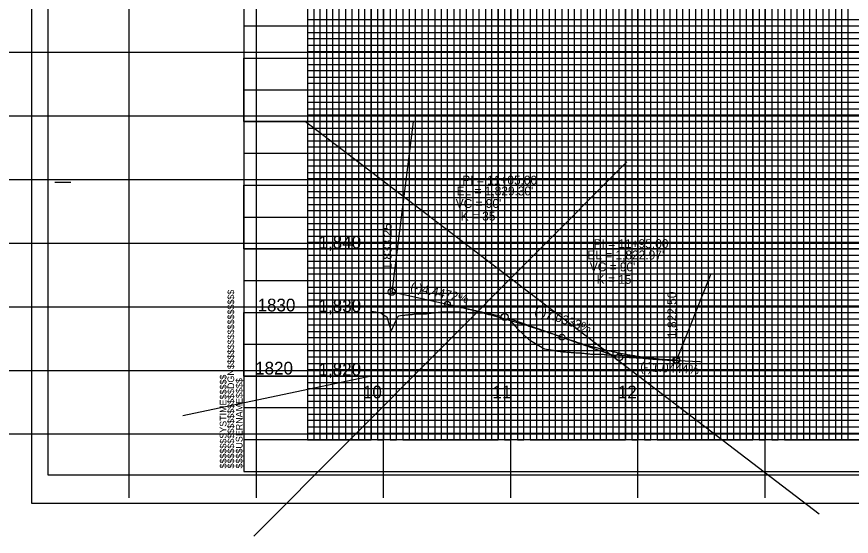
# Model space of a CAD drawing. Extents: x 553912 to 567693, y 512355 to 537539.
# Drawn here: x 559761 to 560417, y 521024 to 521433 of the extents above; entities that cross this region are included whole.
import ezdxf

# ---------------------------------------------------------------- set-up
doc = ezdxf.new("R2010")
doc.units = 0
for name, color, linetype in [('Default', 7, 'Continuous'), ('Exist Vertical Profile Ground Line', 7, 'Continuous'), ('Exist Vertical Profile Horizontal Axis Label Major', 7, 'Continuous'), ('Exist Vertical Profile Vertical Axis Label', 7, 'Continuous'), ('Old_Level_42', 7, 'Continuous'), ('Old_Level_51', 7, 'Continuous'), ('Old_Level_53', 7, 'Continuous'), ('Old_Level_54', 7, 'Continuous'), ('Prop ROW Permanent Easement CELL', 7, 'Continuous'), ('Prop Vertical Profile Curve Label', 7, 'Continuous'), ('Prop Vertical Profile Ditch Grade Right Label', 7, 'Continuous'), ('Prop Vertical Profile Grade', 7, 'Continuous'), ('Prop Vertical Profile Grade Label', 7, 'Continuous'), ('Prop VPI Label', 7, 'Continuous'), ('Sheet Profile Grid Major CELL', 7, 'Continuous'), ('Sheet Row Area Data CELL', 7, 'Continuous'), ('Sheet Summary Guardrail CELL', 7, 'Continuous')]:
    doc.layers.add(name, color=color, linetype=linetype)

msp = doc.modelspace()

# ---------------------------------------------------------------- linework, layer by layer
at = {"layer": 'Default'}
msp.add_lwpolyline([(561456.66, 522150.42), (559772.66, 522150.42), (559772.66, 521050.42), (561456.66, 521050.42)], close=True, dxfattribs=at)
at = {"layer": 'Exist Vertical Profile Ground Line'}
for points in [[(560039.66, 521201.58), (560046.99, 521200.43), (560048.85, 521198.92), (560052.01, 521197.1), (560054.97, 521187.43), (560055.59, 521186.29), (560060.34, 521196.62), (560060.68, 521197.07), (560061.38, 521197.92), (560062.81, 521198.09), (560065.6, 521198.37), (560066.23, 521198.44), (560066.85, 521198.5), (560067.48, 521198.56), (560068.1, 521198.62), (560068.73, 521198.67), (560069.36, 521198.73), (560069.98, 521198.78), (560070.61, 521198.84), (560071.24, 521198.89), (560071.86, 521198.95), (560072.49, 521199.03), (560072.81, 521199.08), (560073.11, 521199.14), (560073.74, 521199.27), (560074.37, 521199.28), (560074.99, 521199.29), (560075.62, 521199.3), (560076.24, 521199.31), (560076.87, 521199.31), (560077.5, 521199.32), (560078.12, 521199.33), (560078.75, 521199.33), (560079.38, 521199.33), (560080, 521199.32), (560080.63, 521199.32), (560081.25, 521199.32), (560081.94, 521199.31), (560082.51, 521199.34), (560083.13, 521199.38), (560083.76, 521199.59), (560084.39, 521199.68), (560085.01, 521199.76), (560085.64, 521199.83), (560086.26, 521199.91), (560086.89, 521199.98), (560087.52, 521200.06), (560088.14, 521200.13), (560088.77, 521200.2), (560089.39, 521200.27), (560090.02, 521200.34), (560090.65, 521200.4), (560091.27, 521200.46), (560091.9, 521200.53), (560092.53, 521200.59), (560093.15, 521200.65), (560093.78, 521200.7), (560094.4, 521200.76), (560095.03, 521200.81), (560095.66, 521200.86), (560096.28, 521200.91), (560096.91, 521200.96), (560097.82, 521201.03), (560098.16, 521201.03), (560098.79, 521201.02), (560099.41, 521201.01), (560100.04, 521201.01), (560100.67, 521201), (560101.29, 521200.99), (560101.92, 521200.99), (560102.24, 521200.98), (560102.54, 521200.98), (560103.17, 521200.98), (560103.8, 521200.97), (560104.42, 521200.97), (560105.05, 521200.96), (560105.68, 521200.96), (560106.3, 521200.95), (560106.93, 521200.95), (560107.55, 521200.94), (560108.18, 521200.93), (560108.81, 521200.89), (560109.43, 521200.84), (560110.06, 521200.8), (560110.68, 521200.75), (560111.31, 521200.7), (560111.94, 521200.65), (560112.56, 521200.6), (560113.19, 521200.55), (560113.82, 521200.49), (560114.44, 521200.43), (560115.07, 521200.38), (560115.84, 521200.3), (560116.32, 521200.28), (560116.95, 521200.25), (560117.57, 521200.22), (560120.57, 521200.06), (560128.05, 521200.17), (560132.8, 521198.9), (560136.5, 521197.84), (560141.43, 521196.57)], [(560141.43, 521196.57), (560148.61, 521194.5), (560149.16, 521194.01), (560149.53, 521193.59), (560154.8, 521187.58), (560163.47, 521179.49), (560164.96, 521178.44), (560175.41, 521172.24), (560176.05, 521171.86), (560179.12, 521171.33), (560180.01, 521171.17), (560180.9, 521171.02), (560181.8, 521170.87), (560182.69, 521170.71), (560183.58, 521170.56), (560184.48, 521170.41), (560185.37, 521170.26), (560186.26, 521170.11), (560187.16, 521169.97), (560188.19, 521169.79), (560188.94, 521169.73), (560189.84, 521169.65), (560190.73, 521169.58), (560191.63, 521169.5), (560192.52, 521169.42), (560193.41, 521169.35), (560194.31, 521169.28), (560195.2, 521169.21), (560196.09, 521169.14), (560196.99, 521169.07), (560197.88, 521169), (560198.77, 521168.93), (560199.67, 521168.87), (560200.56, 521168.81), (560201.45, 521168.76), (560202.35, 521168.7), (560203.24, 521168.64), (560204.13, 521168.59), (560205.03, 521168.54), (560205.92, 521168.48), (560206.81, 521168.38), (560207.71, 521168.28), (560208.6, 521168.18), (560209.5, 521168.08), (560210.39, 521167.99), (560211.28, 521167.89), (560212.18, 521167.79), (560213.07, 521167.72), (560213.96, 521167.71), (560214.86, 521167.71), (560215.75, 521167.7), (560216.64, 521167.69), (560217.54, 521167.69), (560218.43, 521167.68), (560219.32, 521167.67), (560220.22, 521167.67), (560221.26, 521167.67), (560222, 521167.58), (560222.9, 521167.48), (560223.79, 521167.38), (560224.69, 521167.27), (560225.84, 521167.14), (560234.67, 521166.82), (560239.73, 521166.52), (560252.02, 521164.76), (560255.26, 521164.29), (560257.81, 521163.97), (560264.18, 521163.58), (560272.78, 521163.05), (560280.74, 521162.75), (560298.08, 521161.98), (560298.71, 521161.98)]]:
    msp.add_lwpolyline(points, dxfattribs=at)
at = {"layer": 'Old_Level_42'}
for p, q in [((559989.66, 522125.42), (559989.66, 521100.42)), ((560039.66, 522125.42), (560039.66, 521100.42)), ((560089.66, 522125.42), (560089.66, 521100.42)), ((560139.66, 522125.42), (560139.66, 521100.42)), ((560189.66, 522125.42), (560189.66, 521100.42)), ((560239.66, 522125.42), (560239.66, 521100.42)), ((560289.66, 522125.42), (560289.66, 521100.42)), ((560339.66, 522125.42), (560339.66, 521100.42)), ((560389.66, 522125.42), (560389.66, 521100.42)), ((559939.66, 521400.42), (561439.66, 521400.42)), ((559939.66, 521350.42), (561439.66, 521350.42)), ((559939.66, 521300.42), (561439.66, 521300.42)), ((559939.66, 521250.42), (561439.66, 521250.42)), ((559939.66, 521200.42), (561439.66, 521200.42)), ((559939.66, 521150.42), (561439.66, 521150.42))]:
    msp.add_line(p, q, dxfattribs=at)
at = {"layer": 'Old_Level_51'}
msp.add_lwpolyline([(561452.16, 522127.97), (559785.66, 522127.97), (559785.66, 521072.87), (561452.16, 521072.87)], close=True, dxfattribs=at)
at = {"layer": 'Old_Level_53'}
for p, q in [((559791.16, 521302.92), (559803.66, 521302.92)), ((561439.66, 521100.42), (559939.66, 521100.42)), ((559939.66, 521075.42), (559939.66, 521075.42)), ((559939.66, 521075.42), (559939.66, 521075.42)), ((559939.66, 521075.42), (559939.66, 521075.42)), ((559939.66, 521075.42), (559939.66, 521075.42)), ((559939.66, 521075.42), (559939.66, 521075.42)), ((559939.66, 521075.42), (559939.66, 521075.42))]:
    msp.add_line(p, q, dxfattribs=at)
msp.add_lwpolyline([(561439.66, 522125.42), (559939.66, 522125.42), (559939.66, 521075.42), (561439.66, 521075.42)], close=True, dxfattribs=at)
msp.add_lwpolyline([(559977.16, 521075.42), (559977.16, 521075.42)], dxfattribs=at)
at = {"layer": 'Old_Level_54'}
for points in [[(559989.66, 522125.42), (559989.66, 521100.42), (560039.66, 521100.42), (560039.66, 522125.42)], [(560089.66, 522125.42), (560089.66, 521100.42), (560139.66, 521100.42), (560139.66, 522125.42)], [(560189.66, 522125.42), (560189.66, 521100.42), (560239.66, 521100.42), (560239.66, 522125.42)], [(560289.66, 522125.42), (560289.66, 521100.42), (560339.66, 521100.42), (560339.66, 522125.42)], [(560389.66, 522125.42), (560389.66, 521100.42), (560439.66, 521100.42), (560439.66, 522125.42)], [(561439.66, 521350.42), (559939.66, 521350.42), (559939.66, 521400.42), (561439.66, 521400.42)], [(561439.66, 521250.42), (559939.66, 521250.42), (559939.66, 521300.42), (561439.66, 521300.42)], [(561439.66, 521150.42), (559939.66, 521150.42), (559939.66, 521200.42), (561439.66, 521200.42)]]:
    msp.add_lwpolyline(points, dxfattribs=at)
at = {"layer": 'Prop ROW Permanent Easement CELL'}
for points in [[(560014.66, 521100.42), (560014.66, 522125.42)], [(560064.66, 522125.42), (560064.66, 521100.42), (560114.66, 521100.42), (560114.66, 522125.42)], [(560164.66, 522125.42), (560164.66, 521100.42), (560214.66, 521100.42), (560214.66, 522125.42)], [(560264.66, 522125.42), (560264.66, 521100.42), (560314.66, 521100.42), (560314.66, 522125.42)], [(560364.66, 522125.42), (560364.66, 521100.42), (560414.66, 521100.42), (560414.66, 522125.42)], [(561439.66, 521425.42), (559939.66, 521425.42), (559939.66, 521375.42), (561439.66, 521375.42)], [(561439.66, 521325.42), (559939.66, 521325.42), (559939.66, 521275.42), (561439.66, 521275.42)], [(561439.66, 521225.42), (559939.66, 521225.42), (559939.66, 521175.42), (561439.66, 521175.42)], [(561439.66, 521125.42), (559939.66, 521125.42)]]:
    msp.add_lwpolyline(points, dxfattribs=at)
at = {"layer": 'Prop Vertical Profile Curve Label'}
for centre in [(560099.66, 521206.93), (560189.66, 521181.1), (560189.66, 521181.1), (560279.66, 521162.92)]:
    msp.add_circle(centre, 2.25, dxfattribs=at)
at = {"layer": 'Prop Vertical Profile Ditch Grade Right Label'}
msp.add_line((560039.66, 521150.42), (559891.72, 521119.2), dxfattribs=at)
at = {"layer": 'Prop Vertical Profile Grade'}
msp.add_line((560055.84, 521216.67), (560099.66, 521206.93), dxfattribs=at)
for points in [[(560099.66, 521206.93), (560101.46, 521206.53), (560103.26, 521206.12), (560105.06, 521205.71), (560106.86, 521205.29), (560108.66, 521204.87), (560110.46, 521204.44), (560112.26, 521204.01), (560114.06, 521203.58), (560115.86, 521203.14), (560117.66, 521202.69), (560119.46, 521202.24), (560121.26, 521201.79), (560123.06, 521201.33), (560124.86, 521200.87), (560126.66, 521200.4), (560128.46, 521199.93), (560130.26, 521199.45), (560132.06, 521198.97), (560133.86, 521198.48), (560135.66, 521197.99), (560137.46, 521197.5), (560139.26, 521197), (560141.06, 521196.49), (560142.86, 521195.98), (560144.66, 521195.47), (560146.46, 521194.95), (560148.26, 521194.43), (560150.06, 521193.9), (560151.86, 521193.36), (560153.66, 521192.83), (560155.46, 521192.28), (560157.26, 521191.74), (560159.06, 521191.19), (560160.86, 521190.63), (560162.66, 521190.07), (560164.46, 521189.5), (560166.26, 521188.93), (560168.06, 521188.36), (560169.86, 521187.78), (560171.66, 521187.2), (560173.46, 521186.61), (560175.26, 521186.01), (560177.06, 521185.42), (560178.86, 521184.81), (560180.66, 521184.2), (560182.46, 521183.59), (560184.26, 521182.98), (560186.06, 521182.35), (560187.86, 521181.73), (560189.66, 521181.1)], [(560189.66, 521181.1), (560191.46, 521180.47), (560193.26, 521179.85), (560195.06, 521179.25), (560196.86, 521178.65), (560198.66, 521178.07), (560200.46, 521177.49), (560202.26, 521176.93), (560204.06, 521176.38), (560205.86, 521175.84), (560207.66, 521175.31), (560209.46, 521174.79), (560211.26, 521174.28), (560213.06, 521173.78), (560214.86, 521173.29), (560216.66, 521172.82), (560218.46, 521172.35), (560220.26, 521171.89), (560222.06, 521171.45), (560223.86, 521171.02), (560225.66, 521170.59), (560227.46, 521170.18), (560229.26, 521169.78), (560231.06, 521169.39), (560232.86, 521169.01), (560234.66, 521168.64), (560236.46, 521168.28), (560238.26, 521167.94), (560240.06, 521167.6), (560241.86, 521167.27), (560243.66, 521166.96), (560245.46, 521166.65), (560247.26, 521166.36), (560249.06, 521166.08), (560250.86, 521165.81), (560252.66, 521165.55), (560254.46, 521165.3), (560256.26, 521165.06), (560258.06, 521164.83), (560259.86, 521164.61), (560261.66, 521164.4), (560263.46, 521164.21), (560265.26, 521164.02), (560267.06, 521163.85), (560268.86, 521163.68), (560270.66, 521163.53), (560272.46, 521163.39), (560274.26, 521163.25), (560276.06, 521163.13), (560277.86, 521163.02), (560279.66, 521162.92)]]:
    msp.add_spline(points, degree=3, dxfattribs=at)
at = {"layer": 'Prop VPI Label'}
for p, q in [((559988.16, 521350.45), (560392, 521042.13)), ((560072.78, 521350.26), (560055.84, 521216.67)), ((560186.69, 521350.26), (560072.78, 521350.26)), ((559947.48, 521024.5), (560240.64, 521318.9)), ((560306.6, 521230.7), (560279.66, 521162.92)), ((560306.6, 521230.7), (560413.01, 521230.46)), ((560099.66, 521206.93), (560141.98, 521197.52)), ((560189.66, 521181.1), (560147.25, 521196.01)), ((560189.66, 521181.1), (560232.07, 521166.19)), ((560279.66, 521162.92), (560237.41, 521165.13))]:
    msp.add_line(p, q, dxfattribs=at)
for centre in [(560055.84, 521216.67), (560144.66, 521196.92), (560234.66, 521165.27), (560279.66, 521162.92)]:
    msp.add_circle(centre, 2.75, dxfattribs=at)
at = {"layer": 'Sheet Profile Grid Major CELL'}
for p, q in [((559849.45, 521054.67), (559849.45, 522254.67)), ((559949.45, 521054.67), (559949.45, 522254.67)), ((560049.45, 521054.67), (560049.45, 522254.67)), ((560149.45, 521054.67), (560149.45, 522254.67)), ((560249.45, 521054.67), (560249.45, 522254.67)), ((560349.45, 521054.67), (560349.45, 522254.67)), ((563849.45, 521404.67), (557249.45, 521404.67)), ((563849.45, 521354.67), (557249.45, 521354.67)), ((563849.45, 521304.67), (557249.45, 521304.67)), ((563849.45, 521254.67), (557249.45, 521254.67)), ((563849.45, 521204.67), (557249.45, 521204.67)), ((563849.45, 521154.67), (557249.45, 521154.67)), ((563849.45, 521104.67), (557249.45, 521104.67))]:
    msp.add_line(p, q, dxfattribs=at)
at = {"layer": 'Sheet Row Area Data CELL'}
for p, q in [((559772.66, 522150.42), (559772.66, 521050.42)), ((559772.66, 521050.42), (561456.66, 521050.42))]:
    msp.add_line(p, q, dxfattribs=at)
at = {"layer": 'Sheet Summary Guardrail CELL'}
for points in [[(559994.66, 522125.42), (559994.66, 521100.42), (559999.66, 521100.42), (559999.66, 522125.42)], [(560004.66, 522125.42), (560004.66, 521100.42), (560009.66, 521100.42), (560009.66, 522125.42)], [(560019.66, 522125.42), (560019.66, 521100.42), (560024.66, 521100.42), (560024.66, 522125.42)], [(560029.66, 522125.42), (560029.66, 521100.42), (560034.66, 521100.42), (560034.66, 522125.42)], [(560044.66, 522125.42), (560044.66, 521100.42), (560049.66, 521100.42), (560049.66, 522125.42)], [(560054.66, 522125.42), (560054.66, 521100.42), (560059.66, 521100.42), (560059.66, 522125.42)], [(560069.66, 522125.42), (560069.66, 521100.42), (560074.66, 521100.42), (560074.66, 522125.42)], [(560079.66, 522125.42), (560079.66, 521100.42), (560084.66, 521100.42), (560084.66, 522125.42)], [(560094.66, 522125.42), (560094.66, 521100.42), (560099.66, 521100.42), (560099.66, 522125.42)], [(560104.66, 522125.42), (560104.66, 521100.42), (560109.66, 521100.42), (560109.66, 522125.42)], [(560119.66, 522125.42), (560119.66, 521100.42), (560124.66, 521100.42), (560124.66, 522125.42)], [(560129.66, 522125.42), (560129.66, 521100.42), (560134.66, 521100.42), (560134.66, 522125.42)], [(560144.66, 522125.42), (560144.66, 521100.42), (560149.66, 521100.42), (560149.66, 522125.42)], [(560154.66, 521100.42), (560159.66, 521100.42), (560159.66, 522125.42)], [(560154.66, 522125.42), (560154.66, 521100.42)], [(560169.66, 522125.42), (560169.66, 521100.42), (560174.66, 521100.42), (560174.66, 522125.42)], [(560179.66, 522125.42), (560179.66, 521100.42), (560184.66, 521100.42), (560184.66, 522125.42)], [(560194.66, 522125.42), (560194.66, 521100.42), (560199.66, 521100.42), (560199.66, 522125.42)], [(560204.66, 522125.42), (560204.66, 521100.42), (560209.66, 521100.42), (560209.66, 522125.42)], [(560219.66, 522125.42), (560219.66, 521100.42), (560224.66, 521100.42), (560224.66, 522125.42)], [(560229.66, 522125.42), (560229.66, 521100.42), (560234.66, 521100.42), (560234.66, 522125.42)], [(560244.66, 522125.42), (560244.66, 521100.42), (560249.66, 521100.42), (560249.66, 522125.42)], [(560254.66, 522125.42), (560254.66, 521100.42), (560259.66, 521100.42), (560259.66, 522125.42)], [(560269.66, 522125.42), (560269.66, 521100.42), (560274.66, 521100.42), (560274.66, 522125.42)], [(560279.66, 522125.42), (560279.66, 521100.42), (560284.66, 521100.42), (560284.66, 522125.42)], [(560294.66, 522125.42), (560294.66, 521100.42), (560299.66, 521100.42), (560299.66, 522125.42)], [(560304.66, 522125.42), (560304.66, 521100.42), (560309.66, 521100.42), (560309.66, 522125.42)], [(560319.66, 522125.42), (560319.66, 521100.42), (560334.66, 521100.42), (560334.66, 522125.42)], [(560324.66, 522125.42), (560324.66, 521100.42), (560329.66, 521100.42), (560329.66, 522125.42)], [(560324.66, 522124.82), (560324.66, 521100.42), (560329.66, 521100.42), (560329.66, 522124.82)], [(560344.66, 522125.42), (560344.66, 521100.42), (560349.66, 521100.42), (560349.66, 522125.42)], [(560354.66, 522125.42), (560354.66, 521100.42), (560359.66, 521100.42), (560359.66, 522125.42)], [(560369.66, 522125.42), (560369.66, 521100.42), (560374.66, 521100.42), (560374.66, 522125.42)], [(560379.66, 522125.42), (560379.66, 521100.42), (560384.66, 521100.42), (560384.66, 522125.42)], [(560394.66, 522125.42), (560394.66, 521100.42), (560399.66, 521100.42), (560399.66, 522125.42)], [(560404.66, 522125.42), (560404.66, 521100.42), (560409.66, 521100.42), (560409.66, 522125.42)], [(561389.66, 521430.42), (559989.66, 521430.42), (559989.66, 521420.42), (561389.66, 521420.42)], [(561389.66, 521415.42), (559989.66, 521415.42), (559989.66, 521410.42), (561389.66, 521410.42)], [(561389.66, 521405.42), (559989.66, 521405.42), (559989.66, 521395.42), (561389.66, 521395.42)], [(561389.66, 521390.42), (559989.66, 521390.42), (559989.66, 521385.42), (561389.66, 521385.42)], [(561389.66, 521380.42), (559989.66, 521380.42), (559989.66, 521370.42), (561389.66, 521370.42)], [(561389.66, 521365.42), (559989.66, 521365.42), (559989.66, 521360.42), (561389.66, 521360.42)], [(561389.66, 521355.42), (559989.66, 521355.42), (559989.66, 521345.42), (561389.66, 521345.42)], [(561389.66, 521340.42), (559989.66, 521340.42), (559989.66, 521335.42), (561389.66, 521335.42)], [(561389.66, 521330.42), (559989.66, 521330.42), (559989.66, 521320.42), (561389.66, 521320.42)], [(561389.66, 521315.42), (559989.66, 521315.42), (559989.66, 521310.42), (561389.66, 521310.42)], [(561389.66, 521305.42), (559989.66, 521305.42)], [(559989.66, 521295.42), (561389.66, 521295.42)], [(561389.66, 521290.42), (559989.66, 521290.42), (559989.66, 521285.42), (561389.66, 521285.42)], [(561389.66, 521280.42), (559989.66, 521280.42)], [(559989.66, 521270.42), (561389.66, 521270.42)], [(561389.66, 521265.42), (559989.66, 521265.42), (559989.66, 521260.42), (561389.66, 521260.42)], [(561389.66, 521255.42), (559989.66, 521255.42), (559989.66, 521245.42), (561389.66, 521245.42)], [(561389.66, 521240.42), (559989.66, 521240.42), (559989.66, 521235.42), (561389.66, 521235.42)], [(561389.66, 521230.42), (559989.66, 521230.42), (559989.66, 521220.42), (561389.66, 521220.42)], [(561389.66, 521215.42), (559989.66, 521215.42), (559989.66, 521210.42), (561389.66, 521210.42)], [(561389.66, 521205.42), (559989.66, 521205.42), (559989.66, 521195.42), (561389.66, 521195.42)], [(561389.66, 521190.42), (559989.66, 521190.42), (559989.66, 521185.42), (561389.66, 521185.42)], [(561389.66, 521180.42), (559989.66, 521180.42), (559989.66, 521170.42), (561389.66, 521170.42)], [(561389.66, 521165.42), (559989.66, 521165.42), (559989.66, 521160.42), (561389.66, 521160.42)], [(561389.66, 521155.42), (559989.66, 521155.42), (559989.66, 521145.42), (561389.66, 521145.42)], [(561389.66, 521140.42), (559989.66, 521140.42), (559989.66, 521135.42), (561389.66, 521135.42)], [(561389.66, 521130.42), (559989.66, 521130.42), (559989.66, 521120.42), (561389.66, 521120.42)], [(561389.66, 521115.42), (559989.66, 521115.42), (559989.66, 521110.42), (561389.66, 521110.42)], [(561389.66, 521105.42), (559989.66, 521105.42)]]:
    msp.add_lwpolyline(points, dxfattribs=at)

# ---------------------------------------------------------------- texts
at = {"layer": 'Exist Vertical Profile Horizontal Axis Label Major'}
for s, p in [('1830', (559950.39, 521201.27)), ('1820', (559948.49, 521151.67)), ('10', (560033.24, 521132.92)), ('11', (560135.08, 521132.92)), ('12', (560233.63, 521132.92))]:
    msp.add_text(s, height=10, dxfattribs=at).set_placement(p)
at = {"layer": 'Exist Vertical Profile Vertical Axis Label'}
for s, p in [('1,840', (559998.36, 521250.67)), ('1,830', (559998.36, 521200.67)), ('1,820', (559998.36, 521150.67))]:
    msp.add_text(s, height=10, dxfattribs=at).set_placement(p)
at = {"layer": 'Old_Level_53'}
for s, p in [('$$$$$$$$$$$$$$$$DGN$$$$$$$$$$$$$$$$', (559932.01, 521077.79)), ('$$$$$$SYSTIME$$$$$', (559925.96, 521077.79)), ('$$$$USERNAME$$$$', (559938.58, 521077.8))]:
    msp.add_text(s, height=5.25, rotation=90, dxfattribs=at).set_placement(p)
at = {"layer": 'Prop Vertical Profile Curve Label'}
for s, p in [("VC = 90'", (560106.17, 521282.62)), ('K = 35', (560110.09, 521272.68)), ("VC = 90'", (560211.57, 521232.74)), ('K = 15', (560216.99, 521222.95))]:
    msp.add_text(s, height=7, dxfattribs=at).set_placement(p)
at = {"layer": 'Prop Vertical Profile Grade Label'}
for s, rotation, p in [('(-)4.4472%', 347.46368, (560070.11, 521217.6)), ('(-)7.0333%', 340.62493, (560167.61, 521199.59)), ('(-)1.0444%', 357.0106, (560251.03, 521154.4))]:
    msp.add_text(s, height=7, rotation=rotation, dxfattribs=at).set_placement(p)
at = {"layer": 'Prop VPI Label'}
for s, p in [('PI = 11+05.00', (560111.37, 521300.99)), ("EL = 1,829.30'", (560106.89, 521292.43)), ('PI = 11+95.00', (560214.59, 521251.03)), ("EL = 1,822.97'", (560209.69, 521242.14))]:
    msp.add_text(s, height=7, dxfattribs=at).set_placement(p)
for s, p in [('1,833.25', (560055.84, 521234.17)), ('1,822.50', (560279.66, 521180.42))]:
    msp.add_text(s, height=7, rotation=90, dxfattribs=at).set_placement(p)

doc.saveas('drawing.dxf')
